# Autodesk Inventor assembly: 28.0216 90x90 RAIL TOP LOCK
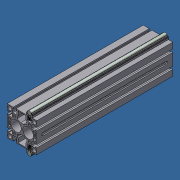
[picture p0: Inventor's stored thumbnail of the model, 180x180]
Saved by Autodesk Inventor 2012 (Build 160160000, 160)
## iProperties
Created: 2011-05
Part Number: 28.0216 90x90 RAIL TOP LOCK
Document SubType Name: Assembly
Designer: Administrator
Author: Administrator
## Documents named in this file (4)
- C:\Andys Backup Data\ANDY'S INVENTOR\INVENTOR LIBRARIES\PARTS LIBRARY\READY FOR USE MODULES LG\SUBCOMPONENTS\28.0216_2 90x90 RAIL TOP LOCK.iam
- C:\Andys Backup Data\ANDY'S INVENTOR\INVENTOR LIBRARIES\PARTS LIBRARY\READY FOR USE MODULES LG\SUBCOMPONENTS\28.0216_3 90x90S TOP LOCK.ipt
- C:\Andys Backup Data\ANDY'S INVENTOR\INVENTOR LIBRARIES\PARTS LIBRARY\READY FOR USE MODULES LG\SUBCOMPONENTS\28.0215_7 SHAFT SUPP PROF TOP LOCK.ipt
- C:\Andys Backup Data\ANDY'S INVENTOR\INVENTOR LIBRARIES\PARTS LIBRARY\READY FOR USE MODULES LG\SUBCOMPONENTS\28.0215_6 SHAFT 12 FOR TOP LOCK.ipt
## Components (5 placed, 3 different names)
1. 28.0216_3 90x90S TOP LOCK:1 — Mate:7, Mate:11, Mate:12, Mate:13, Mate:14
2. 28.0215_7 SHAFT SUPP PROF TOP LOCK:1 — Mate:2, Mate:4, Mate:10, Mate:13
3. 28.0215_7 SHAFT SUPP PROF TOP LOCK:2 — Mate:3, Mate:5, Mate:7, Mate:11
4. 28.0215_6 SHAFT 12 FOR TOP LOCK:1 — Mate:2, Mate:4, Mate:14
5. 28.0215_6 SHAFT 12 FOR TOP LOCK:2 — Mate:3, Mate:5, Mate:12
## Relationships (10: Mate 10)
- Mate:2: 28.0215_7 SHAFT SUPP PROF TOP LOCK:1 ↔ 28.0215_6 SHAFT 12 FOR TOP LOCK:1
- Mate:3: 28.0215_7 SHAFT SUPP PROF TOP LOCK:2 ↔ 28.0215_6 SHAFT 12 FOR TOP LOCK:2
- Mate:4: 28.0215_7 SHAFT SUPP PROF TOP LOCK:1 ↔ 28.0215_6 SHAFT 12 FOR TOP LOCK:1
- Mate:5: 28.0215_7 SHAFT SUPP PROF TOP LOCK:2 ↔ 28.0215_6 SHAFT 12 FOR TOP LOCK:2
- Mate:7: 28.0216_3 90x90S TOP LOCK:1 ↔ 28.0215_7 SHAFT SUPP PROF TOP LOCK:2
- Mate:10: 28.0215_7 SHAFT SUPP PROF TOP LOCK:1
- Mate:11: 28.0216_3 90x90S TOP LOCK:1 ↔ 28.0215_7 SHAFT SUPP PROF TOP LOCK:2
- Mate:12: 28.0216_3 90x90S TOP LOCK:1 ↔ 28.0215_6 SHAFT 12 FOR TOP LOCK:2
- Mate:13: 28.0216_3 90x90S TOP LOCK:1 ↔ 28.0215_7 SHAFT SUPP PROF TOP LOCK:1
- Mate:14: 28.0216_3 90x90S TOP LOCK:1 ↔ 28.0215_6 SHAFT 12 FOR TOP LOCK:1
